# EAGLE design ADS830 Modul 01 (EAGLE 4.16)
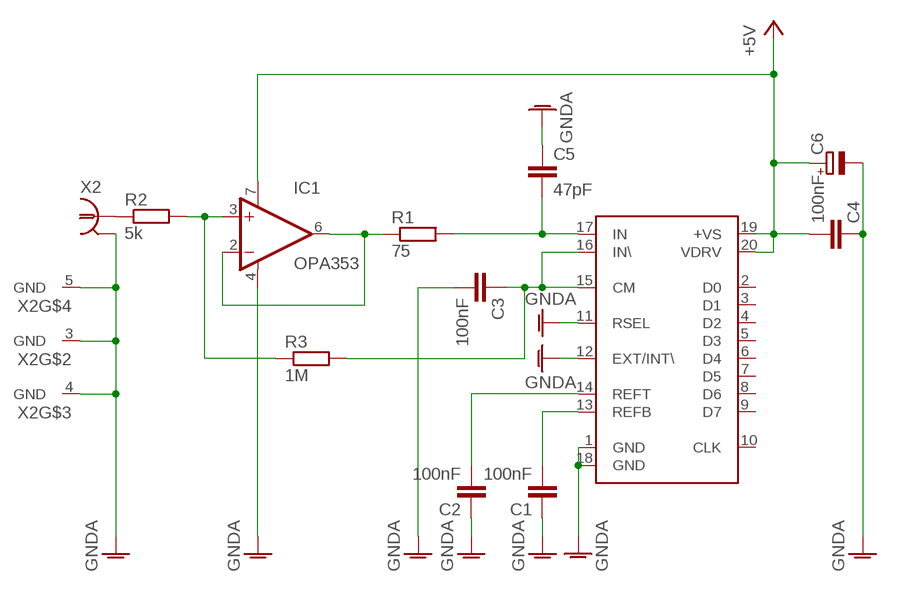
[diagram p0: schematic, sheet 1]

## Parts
C1  100nF  C-EUC0603  [C0603]
C2  100nF  C-EUC0603  [C0603]
C3  100nF  C-EUC0603  [C0603]
C4  100nF  C-EUC0603  [C0603]
C5  47pF  C-EUC0603  [C0603]
C6  CPOL-EU153CLV-0505  [153CLV-0505]
IC1  OPA353  [SO08]
IC2  ADS830  [TSSOP20]
R1  75  R-EU_R0603  [R0603]
R2  5k  R-EU_R0603  [R0603]
R3  1M  R-EU_R0603  [R0603]
X2  BN35N61  [B35N61]

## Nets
+5V: C4.2 C6.+ IC1.7(+VS1) IC2.19(+VS) IC2.20(VDRV)
GNDA: C1.1 C2.1 C3.2 C4.1 C5.1 C6.- IC1.4(-VS1) IC2.1(GND) IC2.11(RSEL) IC2.12(EXT/INT\) IC2.18(GND) X2.2(GND) X2.3(GND) X2.4(GND) X2.5(GND)
N$1: IC1.3(+IN) R2.2 R3.1
N$2: R2.1 X2.1
N$3: IC1.2(-IN) IC1.6(OUT) R1.1
N$5: C5.2 IC2.17(IN) R1.2
N$6: C3.1 IC2.15(CM) IC2.16(IN\) R3.2
N$8: C1.2 IC2.13(REFB)
N$9: C2.2 IC2.14(REFT)
Unconnected: IC2.2(D0) IC2.3(D1) IC2.4(D2) IC2.5(D3) IC2.6(D4) IC2.7(D5) IC2.8(D6) IC2.9(D7) IC2.10(CLK)

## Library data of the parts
C1-C5 = rcl:C-EU: CAPACITOR, European symbol
C6 = rcl:CPOL-EU: POLARIZED CAPACITOR, European symbol
IC1 = selfmade:OPA353
IC2 = selfmade:ADS830
R1-R3 = rcl:R-EU_: RESISTOR, European symbol
X2 = con-coax:BN35N61: BNC CONNECTOR M/A COM www.macom.com distributor Farnell 149-452

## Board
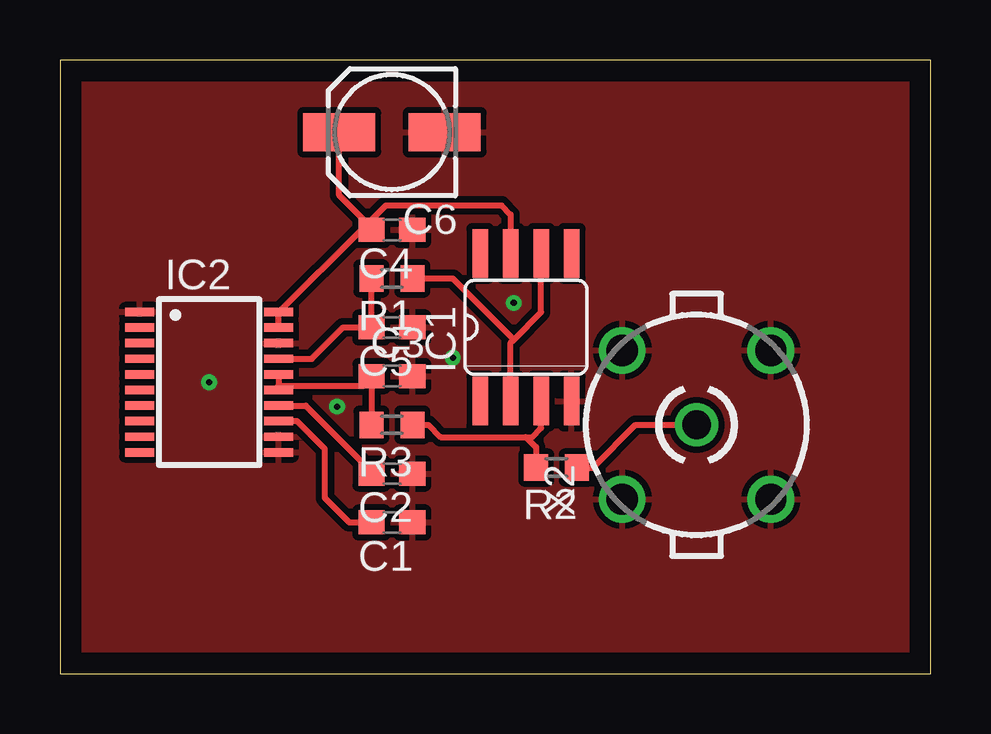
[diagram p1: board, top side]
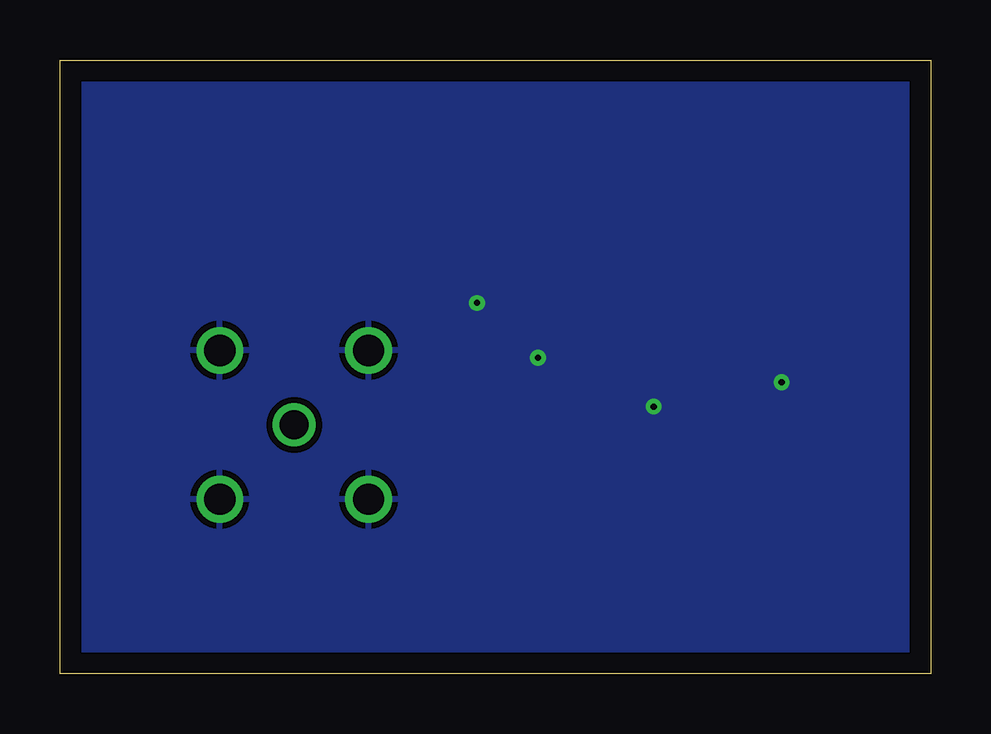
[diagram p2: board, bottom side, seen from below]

Size 36.3 x 25.58 mm. Coordinates in mm from the lower left corner, seen from the top.
Outline: 0,0 36.3,0 36.3,25.58 0,25.58 0,0
Copper layers (1*16): Top 0.035mm / dielectric 1.5mm / Bottom 0.035mm
Design rules "Tom-Ic": minimum track width 6mil, minimum drill 10mil, track to track 10mil, track to pad 10mil, pad to pad 10mil, via to via 10mil, smd to smd 0mil, copper to edge 35mil, drill to drill 8mil, minimum pad ring 10mil, minimum via ring 8mil, stop-mask expansion 4mil, vias tented up to drill 0mil, thermal gap 10mil

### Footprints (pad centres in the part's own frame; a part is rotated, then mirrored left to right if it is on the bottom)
C0603 = smd 1.1 x 1: 1 -0.85,0; 2 0.85,0
153CLV-0505 = smd 3 x 1.6: + 2.2,0; - -2.2,0
SO08 = smd 0.66 x 2.032: 1 -1.905,-3.073; 2 -0.635,-3.073; 3 0.635,-3.073; 4 1.905,-3.073; 5 1.905,3.073; 6 0.635,3.073; 7 -0.635,3.073; 8 -1.905,3.073
TSSOP20 = smd 0.35 x 1.2: 1 -2.925,-2.9; 2 -2.275,-2.9; 3 -1.625,-2.9; 4 -0.975,-2.9; 5 -0.325,-2.9; 6 0.325,-2.9; 7 0.975,-2.9; 8 1.625,-2.9; 9 2.275,-2.9; 10 2.925,-2.9; 11 2.925,2.9; 12 2.275,2.9; 13 1.625,2.9; 14 0.975,2.9; 15 0.325,2.9; 16 -0.325,2.9; 17 -0.975,2.9; 18 -1.625,2.9; 19 -2.275,2.9; 20 -2.925,2.9
R0603 = smd 1 x 1.1: 1 -0.85,0; 2 0.85,0
B35N61 = drill 1.2 round: 1 0,0 | drill 1.3 round: 2 3.099,3.099; 3 -3.099,3.099; 4 -3.099,-3.099; 5 3.099,-3.099

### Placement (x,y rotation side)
C1  13.84,6.31 180 top
C2  13.84,8.34 180 top
C3  13.84,12.41 0 top
C4  13.84,18.5 180 top
C5  13.84,14.44 180 top
C6  13.84,22.57 180 top
IC1  19.43,14.44 0 top
IC2  6.22,12.15 270 top
R1  13.84,16.47 180 top
R2  20.7,8.6 180 top
R3  13.84,10.38 180 top
X2  26.54,10.38 90 top

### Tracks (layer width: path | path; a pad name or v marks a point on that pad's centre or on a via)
+5V
  Top 0.254: 9.14,15.08 9.27,15.2 | IC2.19 9.12,15.05 9.14,15.08 | 9.14,15.08 IC2.20 | C4.2 12.57,18.5 9.14,15.08 | C4.2 13.08,18.5 12.82,18.76 | C6.+ 11.64,19.94 12.82,18.76 | IC1.7 18.79,19.14 18.41,19.52 13.58,19.52 12.82,18.76 | 12.82,18.76 12.99,18.59 C4.2
GNDA  (via drill 0.25)
  other vias: 16.38,13.17 11.55,11.14 18.92,15.46 6.22,12.15
  pour Top (isolate 0.254): 0.12,-0.04 36.19,-0.04 36.19,25.62 0.12,25.62
  pour Bottom (isolate 0.254): 0.12,-0.04 36.19,-0.04 36.19,25.62 0.12,25.62
N$1
  Top 0.254: R3.1 15.36,10.38 15.87,9.87 19.43,9.87 | IC1.3 20.06,10.25 19.68,9.87 19.43,9.87 | R2.2 19.85,9.45 19.43,9.87
N$2
  Top 0.254: R2.1 22.22,8.6 24,10.38 X2.1
N$3
  Top 0.254: IC1.2 18.79,13.8 18.92,13.93 | IC1.6 20.06,15.07 18.92,13.93 | R1.1 16.38,16.47 18.92,13.93
N$5
  Top 0.254: IC2.17 10.5,13.13 11.81,14.44 C5.2 13.08,14.44 12.99,14.53 R1.2
N$6
  Top 0.254: IC2.15 9.08,11.83 9.01,11.9 9.12,12.01 | IC2.16 9.12,12.01 | 9.12,12.01 12.67,12.01 13.08,12.41 C3.1 12.99,12.24 13.08,12.15 12.99,12.07 R3.2
N$8
  Top 0.254: IC2.13 9.88,10.53 11.04,9.36 11.04,7.33 12.06,6.31 C1.2
N$9
  Top 0.254: IC2.14 10.24,11.18 12.99,8.43 C2.2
